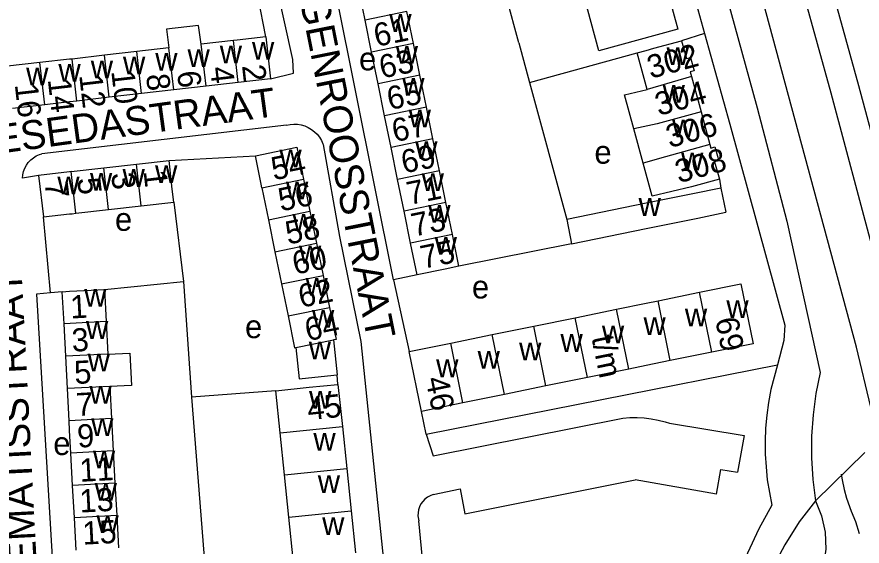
# Model space of a CAD drawing. Extents: x 161258 to 163262, y 380749 to 382054.
# Drawn here: x 162490.8 to 162637.4, y 380827.3 to 380919 of the extents above; entities that cross this region are included whole.
import ezdxf

# ---------------------------------------------------------------- set-up
doc = ezdxf.new("R2010")
doc.units = 0
for name, color, linetype in [('BLT_Basislijn', 7, 'Continuous'), ('BLT_Bebouwing', 7, 'Continuous'), ('BLT_Centroide', 7, 'Continuous'), ('BLT_Huisnummer', 7, 'Continuous'), ('BLT_Huisnummer_ tussenligend', 7, 'Continuous'), ('BLT_Huisnummer_reeks', 7, 'Continuous'), ('BLT_Onderverdeling_panden', 7, 'Continuous'), ('BLT_Straatnaam', 7, 'Continuous'), ('BLT_Vlakafsluiter', 7, 'Continuous')]:
    doc.layers.add(name, color=color, linetype=linetype)

msp = doc.modelspace()

# ---------------------------------------------------------------- linework, layer by layer
at = {"layer": 'BLT_Basislijn'}
for p, q in [((162598.33, 380979.15), (162619.24, 380903.22)), ((162556.16, 380873.4), (162542.82, 380939.78)), ((162534.01, 380915.53), (162531.16, 380930.59)), ((162607.47, 380925.62), (162610.11, 380916.11)), ((162610.11, 380916.11), (162606.13, 380914.84)), ((162610.11, 380916.11), (162614.47, 380900.39)), ((162577.91, 380914.48), (162579.77, 380907.59)), ((162579.77, 380907.59), (162598.43, 380912.72)), ((162579.77, 380907.59), (162586.2, 380883.87)), ((162537.6, 380900.21), (162495.18, 380895.26)), ((162543.96, 380896.85), (162546.79, 380880.94)), ((162517.24, 380894.1), (162532.21, 380894.93)), ((162494.62, 380891.52), (162491.83, 380891.02)), ((162612.68, 380890.86), (162612.96, 380889.32)), ((162518.06, 380886.89), (162519.76, 380873.16)), ((162496.7, 380871.17), (162495.44, 380884.31)), ((162624.37, 380883.59), (162630.17, 380857.39)), ((162587.05, 380879.68), (162567.49, 380875.77)), ((162506.03, 380871.77), (162519.76, 380873.16)), ((162519.76, 380873.16), (162521.15, 380853.1)), ((162560.26, 380874.29), (162556.16, 380873.4)), ((162498.72, 380871.37), (162496.7, 380871.17)), ((162561.8, 380846.66), (162622.75, 380858.69)), ((162546.52, 380855.31), (162546.4, 380856.96)), ((162535.76, 380854.2), (162521.15, 380853.1)), ((162521.15, 380853.1), (162525.29, 380800.38)), ((162561.8, 380846.66), (162561.02, 380850.63)), ((162604.05, 380848.58), (162616.95, 380846.46)), ((162616.95, 380846.46), (162615.82, 380840.08)), ((162612.19, 380836.29), (162612.94, 380840.58)), ((162612.94, 380840.58), (162615.82, 380840.08)), ((162568.53, 380832.9), (162598.07, 380838.79)), ((162612.19, 380836.29), (162598.07, 380838.79)), ((162563.03, 380836.22), (162567.74, 380837.19)), ((162567.74, 380837.19), (162568.53, 380832.9)), ((162565.87, 380776.71), (162560.55, 380831.67))]:
    msp.add_line(p, q, dxfattribs=at)
for points in [[(162639.76, 380896.31), (162636.88, 380907.05), (162625.03, 380949.86)], [(162639.3, 380878.73), (162632.06, 380905.74), (162620.21, 380948.53)], [(162638.95, 380851.39), (162636.45, 380861.75), (162620.19, 380921.84), (162616.59, 380932.76)], [(162534.85, 380908.26), (162538.82, 380909.25), (162538.71, 380911.61), (162534.34, 380931.24)], [(162619.24, 380903.22), (162624.37, 380883.59)], [(162537.6, 380900.21), (162538.23, 380900.34), (162538.88, 380900.4), (162539.53, 380900.37), (162540.17, 380900.26), (162540.79, 380900.08), (162541.38, 380899.82), (162541.94, 380899.49), (162542.45, 380899.09), (162542.91, 380898.64), (162543.31, 380898.13), (162543.65, 380897.57), (162543.91, 380896.98), (162543.96, 380896.85)], [(162614.47, 380900.39), (162624.02, 380865.55), (162623.84, 380862.9), (162622.75, 380858.69)], [(162491.83, 380891.02), (162491.88, 380891.61), (162492, 380892.19), (162492.21, 380892.75), (162492.49, 380893.28), (162492.83, 380893.77), (162493.24, 380894.2), (162493.7, 380894.58), (162494.21, 380894.89), (162494.76, 380895.13), (162495.18, 380895.26)], [(162546.79, 380880.94), (162550.5, 380862.73), (162559.51, 380775.73)], [(162556.16, 380873.4), (162558.9, 380861.01)], [(162496.7, 380871.17), (162494.25, 380870.92), (162498.58, 380798.22)], [(162622.75, 380858.69), (162622.16, 380856.55), (162621.61, 380854.4), (162621.21, 380852.19), (162620.89, 380849.97), (162620.7, 380847.73), (162620.61, 380845.49), (162620.62, 380843.24), (162620.77, 380841), (162620.99, 380838.77), (162621.38, 380836.58), (162621.79, 380834.4)], [(162630.17, 380857.39), (162629.43, 380853.74), (162628.93, 380850.04), (162628.67, 380846.31), (162628.65, 380842.57), (162628.87, 380838.84), (162629.33, 380835.15)], [(162561.8, 380846.66), (162563.05, 380842.92), (162595.92, 380849.46)], [(162595.92, 380849.46), (162597.15, 380849.55), (162598.4, 380849.57), (162599.63, 380849.5), (162600.87, 380849.35), (162602.08, 380849.12), (162603.29, 380848.82), (162604.05, 380848.58)], [(162633.8, 380839.73), (162633.99, 380838.75), (162634.34, 380837.1), (162634.75, 380835.6), (162635.53, 380833.37), (162636.26, 380831.57), (162636.92, 380829.5)], [(162563.03, 380836.22), (162562.52, 380836.02), (162562.05, 380835.76), (162561.62, 380835.42), (162561.24, 380835.03), (162560.93, 380834.59), (162560.68, 380834.1), (162560.51, 380833.59), (162560.42, 380833.05), (162560.41, 380832.51), (162560.47, 380831.97), (162560.55, 380831.67)], [(162629.33, 380835.15), (162626.53, 380831.47), (162624.01, 380827.51), (162621.79, 380823.32), (162619.91, 380818.92), (162618.39, 380814.35), (162617.25, 380809.66), (162616.51, 380804.91), (162616.17, 380800.13), (162616.22, 380795.39), (162616.65, 380790.72), (162617.56, 380786.03)], [(162629.33, 380835.15), (162630.39, 380832.54), (162631.01, 380829.7), (162631.13, 380826.75), (162630.72, 380823.82), (162629.82, 380821.06), (162628.51, 380818.56)], [(162621.79, 380834.4), (162619.55, 380830.31), (162617.54, 380826.05), (162615.78, 380821.65), (162614.29, 380817.14), (162613.06, 380812.53), (162612.12, 380807.85), (162611.47, 380803.12), (162611.11, 380798.38), (162611.04, 380793.64), (162611.25, 380788.94), (162611.74, 380784.3)]]:
    msp.add_lwpolyline(points, dxfattribs=at)
at = {"layer": 'BLT_Bebouwing'}
for p, q in [((162577.91, 380914.48), (162572.74, 380933.25)), ((162551.24, 380918.41), (162550.12, 380923.92)), ((162559.61, 380914.37), (162558.48, 380919.89)), ((162552.37, 380912.89), (162551.24, 380918.41)), ((162528.42, 380914.89), (162522.82, 380914.25)), ((162534.01, 380915.53), (162534.85, 380908.26)), ((162560.74, 380908.86), (162559.61, 380914.37)), ((162511.63, 380912.96), (162506.03, 380912.32)), ((162517.22, 380913.6), (162511.63, 380912.96)), ((162553.5, 380907.38), (162552.37, 380912.89)), ((162506.03, 380912.32), (162500.43, 380911.67)), ((162494.83, 380911.05), (162489.24, 380910.41)), ((162561.86, 380903.34), (162560.74, 380908.86)), ((162607.84, 380908.67), (162609.51, 380902.52)), ((162523.66, 380906.97), (162518.06, 380906.33)), ((162529.25, 380907.61), (162523.66, 380906.97)), ((162534.85, 380908.26), (162529.25, 380907.61)), ((162554.62, 380901.86), (162553.5, 380907.38)), ((162512.46, 380905.68), (162506.87, 380905.04)), ((162518.06, 380906.33), (162512.46, 380905.68)), ((162506.87, 380905.04), (162501.27, 380904.4)), ((162495.67, 380903.76), (162490.07, 380903.12)), ((162562.99, 380897.83), (162561.86, 380903.34)), ((162609.51, 380902.52), (162611.05, 380896.85)), ((162555.75, 380896.35), (162554.62, 380901.86)), ((162599.46, 380893.66), (162597.85, 380899.56)), ((162564.12, 380892.31), (162562.99, 380897.83)), ((162556.88, 380890.83), (162555.75, 380896.35)), ((162511.58, 380893.46), (162517.24, 380894.1)), ((162500.27, 380892.17), (162505.93, 380892.81)), ((162505.93, 380892.81), (162511.58, 380893.46)), ((162565.24, 380886.8), (162564.12, 380892.31)), ((162494.62, 380891.52), (162495.44, 380884.31)), ((162540.54, 380890.85), (162541.68, 380885.3)), ((162558, 380885.32), (162556.88, 380890.83)), ((162533.34, 380889.38), (162534.47, 380883.83)), ((162612.96, 380889.32), (162613.82, 380885.13)), ((162512.4, 380886.25), (162518.06, 380886.89)), ((162566.37, 380881.28), (162565.24, 380886.8)), ((162501.09, 380884.96), (162506.75, 380885.6)), ((162506.75, 380885.6), (162512.4, 380886.25)), ((162541.68, 380885.3), (162542.81, 380879.75)), ((162559.13, 380879.8), (162558, 380885.32)), ((162534.47, 380883.83), (162535.6, 380878.28)), ((162586.2, 380883.87), (162587.05, 380879.68)), ((162567.49, 380875.77), (162566.37, 380881.28)), ((162542.81, 380879.75), (162543.94, 380874.2)), ((162560.26, 380874.29), (162559.13, 380879.8)), ((162535.6, 380878.28), (162536.74, 380872.73)), ((162543.94, 380874.2), (162545.07, 380868.65)), ((162506.03, 380871.77), (162506.33, 380866.18)), ((162536.74, 380872.73), (162537.87, 380867.18)), ((162499.02, 380865.78), (162498.72, 380871.37)), ((162602.05, 380869.79), (162609.24, 380871.26)), ((162587.67, 380866.86), (162594.86, 380868.33)), ((162506.33, 380866.18), (162506.64, 380860.57)), ((162580.48, 380865.4), (162587.67, 380866.86)), ((162499.32, 380860.18), (162499.02, 380865.78)), ((162573.29, 380863.93), (162580.48, 380865.4)), ((162545.78, 380863), (162546.4, 380856.96)), ((162566.1, 380862.47), (162573.29, 380863.93)), ((162558.9, 380861.01), (162566.1, 380862.47)), ((162618.53, 380862.35), (162611.35, 380860.88)), ((162499.61, 380854.58), (162499.32, 380860.18)), ((162561.02, 380850.63), (162558.9, 380861.01)), ((162611.35, 380860.88), (162604.16, 380859.42)), ((162596.97, 380857.96), (162589.78, 380856.49)), ((162589.78, 380856.49), (162582.59, 380855.03)), ((162499.91, 380848.97), (162499.61, 380854.58)), ((162506.94, 380854.97), (162507.25, 380849.37)), ((162536.51, 380846.91), (162535.76, 380854.2)), ((162546.52, 380855.31), (162547.29, 380848.02)), ((162582.59, 380855.03), (162575.4, 380853.56)), ((162575.4, 380853.56), (162568.21, 380852.1)), ((162568.21, 380852.1), (162561.02, 380850.63)), ((162507.25, 380849.37), (162507.55, 380843.77)), ((162537.26, 380839.61), (162536.51, 380846.91)), ((162547.29, 380848.02), (162548.05, 380840.72)), ((162500.52, 380837.77), (162500.21, 380843.37)), ((162507.55, 380843.77), (162507.86, 380838.17)), ((162538.01, 380832.31), (162537.26, 380839.61)), ((162548.05, 380840.72), (162548.81, 380833.42)), ((162507.86, 380838.17), (162508.16, 380832.57)), ((162500.82, 380832.17), (162500.52, 380837.77)), ((162501.13, 380826.57), (162500.82, 380832.17)), ((162508.16, 380832.57), (162508.46, 380826.97)), ((162538.77, 380825.01), (162538.01, 380832.31)), ((162548.81, 380833.42), (162549.57, 380826.12))]:
    msp.add_line(p, q, dxfattribs=at)
msp.add_lwpolyline([(162586.62, 380932.14), (162600.29, 380935.87), (162605.47, 380916.82), (162591.8, 380913.09)], close=True, dxfattribs=at)
for points in [[(162522.82, 380914.25), (162522.37, 380917.48), (162516.8, 380916.84), (162517.22, 380913.6)], [(162534.01, 380915.53), (162529.04, 380914.96), (162528.42, 380914.89)], [(162598.43, 380912.72), (162600, 380913.16), (162601.31, 380913.53), (162606.13, 380914.84)], [(162606.13, 380914.84), (162606.97, 380911.76), (162607.68, 380911.95), (162608.32, 380909.63), (162607.63, 380909.44), (162607.84, 380908.67)], [(162600.14, 380906.41), (162598.43, 380912.72)], [(162500.43, 380911.67), (162500, 380911.65), (162494.83, 380911.05)], [(162597.85, 380899.56), (162596.24, 380905.5), (162600.14, 380906.41)], [(162501.27, 380904.4), (162500, 380904.26), (162495.67, 380903.76)], [(162611.05, 380896.85), (162611.21, 380896.25), (162611.92, 380896.44), (162612.57, 380894.04), (162611.86, 380893.85), (162612.68, 380890.86)], [(162532.21, 380894.93), (162539.41, 380896.4), (162540.54, 380890.85)], [(162518.06, 380886.89), (162517.8, 380889.13), (162517.24, 380894.1)], [(162533.34, 380889.38), (162533.21, 380890), (162532.21, 380894.93)], [(162612.68, 380890.86), (162607.85, 380889.55), (162601.02, 380887.91), (162599.46, 380893.66)], [(162500.27, 380892.17), (162500, 380892.14), (162494.62, 380891.52)], [(162612.96, 380889.32), (162608.06, 380888.32), (162600, 380886.68), (162586.2, 380883.87)], [(162495.44, 380884.31), (162500, 380884.83), (162500.41, 380884.88), (162501.09, 380884.96)], [(162587.05, 380879.68), (162600, 380882.32), (162608.92, 380884.13), (162613.82, 380885.13)], [(162567.49, 380875.77), (162565.15, 380875.29), (162560.26, 380874.29)], [(162498.72, 380871.37), (162500, 380871.44), (162503.72, 380871.65), (162506.03, 380871.77)], [(162609.24, 380871.26), (162616.42, 380872.72), (162618.53, 380862.35)], [(162594.86, 380868.33), (162600, 380869.38), (162602.05, 380869.79)], [(162545.07, 380868.65), (162546.21, 380863.09), (162545.78, 380863)], [(162537.87, 380867.18), (162539, 380861.63), (162539.25, 380861.68)], [(162539.25, 380861.68), (162539.81, 380856.28), (162541.43, 380856.45), (162546.4, 380856.96)], [(162506.64, 380860.57), (162510.45, 380860.69), (162510.75, 380855.11), (162506.94, 380854.97)], [(162604.16, 380859.42), (162600, 380858.57), (162596.97, 380857.96)], [(162535.76, 380854.2), (162541.55, 380854.8), (162546.52, 380855.31)], [(162500.21, 380843.37), (162500, 380847.3), (162499.91, 380848.97)]]:
    msp.add_lwpolyline(points, dxfattribs=at)
at = {"layer": 'BLT_Onderverdeling_panden'}
for p, q in [((162558.48, 380919.89), (162551.24, 380918.41)), ((162523.66, 380906.97), (162522.82, 380914.25)), ((162529.25, 380907.61), (162528.42, 380914.89)), ((162559.61, 380914.37), (162552.37, 380912.89)), ((162512.46, 380905.68), (162511.63, 380912.96)), ((162518.06, 380906.33), (162517.22, 380913.6)), ((162501.27, 380904.4), (162500.43, 380911.67)), ((162506.87, 380905.04), (162506.03, 380912.32)), ((162495.67, 380903.76), (162494.83, 380911.05)), ((162560.74, 380908.86), (162553.5, 380907.38)), ((162607.84, 380908.67), (162600.14, 380906.41)), ((162561.86, 380903.34), (162554.62, 380901.86)), ((162562.99, 380897.83), (162555.75, 380896.35)), ((162506.75, 380885.6), (162505.93, 380892.81)), ((162512.4, 380886.25), (162511.58, 380893.46)), ((162564.12, 380892.31), (162556.88, 380890.83)), ((162501.09, 380884.96), (162500.27, 380892.17)), ((162533.34, 380889.38), (162540.54, 380890.85)), ((162565.24, 380886.8), (162558, 380885.32)), ((162534.47, 380883.83), (162541.68, 380885.3)), ((162566.37, 380881.28), (162559.13, 380879.8)), ((162535.6, 380878.28), (162542.81, 380879.75)), ((162536.74, 380872.73), (162543.94, 380874.2)), ((162611.35, 380860.88), (162609.24, 380871.26)), ((162604.16, 380859.42), (162602.05, 380869.79)), ((162537.87, 380867.18), (162545.07, 380868.65)), ((162596.97, 380857.96), (162594.86, 380868.33)), ((162506.33, 380866.18), (162499.02, 380865.78)), ((162589.78, 380856.49), (162587.67, 380866.86)), ((162582.59, 380855.03), (162580.48, 380865.4)), ((162539.25, 380861.68), (162545.78, 380863)), ((162575.4, 380853.56), (162573.29, 380863.93)), ((162568.21, 380852.1), (162566.1, 380862.47)), ((162506.64, 380860.57), (162499.32, 380860.18)), ((162506.94, 380854.97), (162499.61, 380854.58)), ((162507.25, 380849.37), (162499.91, 380848.97)), ((162536.51, 380846.91), (162547.29, 380848.02)), ((162507.55, 380843.77), (162500.21, 380843.37)), ((162537.26, 380839.61), (162548.05, 380840.72)), ((162507.86, 380838.17), (162500.52, 380837.77)), ((162508.16, 380832.57), (162500.82, 380832.17)), ((162538.01, 380832.31), (162548.81, 380833.42))]:
    msp.add_line(p, q, dxfattribs=at)
for points in [[(162609.51, 380902.52), (162601.88, 380900.42), (162597.85, 380899.56)], [(162611.05, 380896.85), (162603.31, 380894.75), (162599.46, 380893.66)]]:
    msp.add_lwpolyline(points, dxfattribs=at)
at = {"layer": 'BLT_Vlakafsluiter'}
msp.add_line((162637.88, 380843.51), (162629.33, 380835.15), dxfattribs=at)

# ---------------------------------------------------------------- texts
at = {"layer": 'BLT_Centroide'}
for s, p in [('w', (162555.43, 380916.38)), ('w', (162531.62, 380911.56)), ('w', (162514.84, 380909.66)), ('w', (162520.44, 380910.28)), ('w', (162526.03, 380910.94)), ('e', (162550.19, 380909.71)), ('w', (162556.55, 380910.88)), ('w', (162603.52, 380910.62)), ('w', (162503.66, 380908.34)), ('w', (162509.25, 380909)), ('w', (162492.45, 380907.09)), ('w', (162498.05, 380907.73)), ('w', (162557.68, 380905.34)), ('w', (162602.84, 380904.12)), ('w', (162558.8, 380899.84)), ('w', (162604.48, 380898.09)), ('w', (162559.93, 380894.34)), ('e', (162591.01, 380893.54)), ('w', (162536.38, 380892.91)), ('w', (162606.04, 380892.38)), ('w', (162509.17, 380889.53)), ('w', (162514.81, 380890.17)), ('w', (162497.86, 380888.25)), ('w', (162503.52, 380888.88)), ('w', (162561.05, 380888.81)), ('w', (162537.51, 380887.34)), ('w', (162562.19, 380883.31)), ('w', (162598.67, 380884.5)), ('e', (162507.86, 380881.91)), ('w', (162538.64, 380881.78)), ('w', (162563.31, 380877.78)), ('w', (162539.77, 380876.25)), ('w', (162540.91, 380870.69)), ('e', (162569.77, 380870.19)), ('w', (162502.52, 380868.78)), ('w', (162613.89, 380866.81)), ('w', (162542.03, 380865.12)), ('w', (162606.7, 380865.34)), ('w', (162502.83, 380863.19)), ('e', (162530.42, 380863.32)), ('w', (162599.52, 380863.88)), ('w', (162592.31, 380862.41)), ('w', (162585.12, 380860.94)), ('w', (162541.46, 380859.66)), ('w', (162577.94, 380859.47)), ('w', (162503.12, 380857.56)), ('w', (162570.75, 380858.02)), ('w', (162563.56, 380856.55)), ('w', (162503.43, 380851.97)), ('w', (162541.52, 380851.09)), ('w', (162503.73, 380846.38)), ('w', (162542.27, 380843.81)), ('e', (162497.16, 380843.07)), ('w', (162504.04, 380840.78)), ('w', (162543.03, 380836.5)), ('w', (162504.34, 380835.16)), ('w', (162504.65, 380829.56)), ('w', (162543.79, 380829.22))]:
    msp.add_text(s, height=4, dxfattribs=at).set_placement(p)
at = {"layer": 'BLT_Huisnummer'}
for s, rotation, p in [('61', 11.5472, (162553.18, 380913.77)), ('302', 15.2006, (162600.77, 380908.23)), ('2', 276.5511, (162529.88, 380910.52)), ('10', 276.5529, (162507.21, 380909.58)), ('6', 276.5442, (162518.62, 380909.45)), ('14', 276.5451, (162496.2, 380908.12)), ('65', 11.5472, (162555.47, 380902.82)), ('69', 11.5396, (162557.93, 380891.83)), ('54', 11.5331, (162535.39, 380890.64)), ('308', 15.2149, (162605.62, 380890.14)), ('1', 276.4981, (162512.8, 380892.25)), ('7', 276.5041, (162495.65, 380890.32)), ('58', 11.527, (162537.85, 380879.51)), ('75', 11.5481, (162561.27, 380875.31)), ('1', 3.113, (162500.2, 380866.71)), ('64', 11.482, (162541.23, 380862.78)), ('5', 3.1071, (162500.89, 380855.36)), ('9', 3.1111, (162501.4, 380844.34)), ('13', 3.1115, (162501.78, 380833.09))]:
    msp.add_text(s, height=4, rotation=rotation, dxfattribs=at).set_placement(p)
at = {"layer": 'BLT_Huisnummer_ tussenligend'}
for s, rotation, p in [('63', 11.5472, (162554.13, 380908.29)), ('4', 276.5511, (162524.32, 380910.19)), ('12', 276.5529, (162501.65, 380908.87)), ('8', 276.5442, (162513.24, 380908.93)), ('16', 276.5451, (162490.47, 380907.25)), ('304', 15.2006, (162602.14, 380901.8)), ('67', 11.5472, (162556.33, 380897.26)), ('306', 15.2006, (162604.05, 380896.24)), ('5', 276.4981, (162501.3, 380890.96)), ('3', 276.4981, (162507.2, 380891.83)), ('71', 11.5396, (162558.9, 380886.37)), ('56', 11.5331, (162536.61, 380885.26)), ('73', 11.5396, (162559.68, 380880.89)), ('60', 11.527, (162539.06, 380874.29)), ('62', 11.527, (162540.11, 380868.56)), ('3', 3.113, (162500.45, 380860.96)), ('7', 3.1071, (162501.22, 380849.8)), ('11', 3.1111, (162501.79, 380838.42)), ('15', 3.1115, (162502.3, 380827.53))]:
    msp.add_text(s, height=4, rotation=rotation, dxfattribs=at).set_placement(p)
at = {"layer": 'BLT_Huisnummer_reeks'}
for s, rotation, p in [('69', 281.5159, (162611.93, 380866.55)), ('t/m', 281.5095, (162590.49, 380863.43)), ('46', 281.518, (162561.69, 380856.28)), ('45', 5.8822, (162541.4, 380849.1))]:
    msp.add_text(s, height=4, rotation=rotation, dxfattribs=at).set_placement(p)
at = {"layer": 'BLT_Straatnaam'}
for s, rotation, p in [('WILGENROOSSTRAAT', 281.2139, (162537.55, 380933.87)), ('RESEDASTRAAT', 7.7154, (162482.59, 380894.57)), ('CLEMATISSTRAAT', 92.9642, (162494.75, 380815.34))]:
    msp.add_text(s, height=5, rotation=rotation, dxfattribs=at).set_placement(p)

doc.saveas('drawing.dxf')
